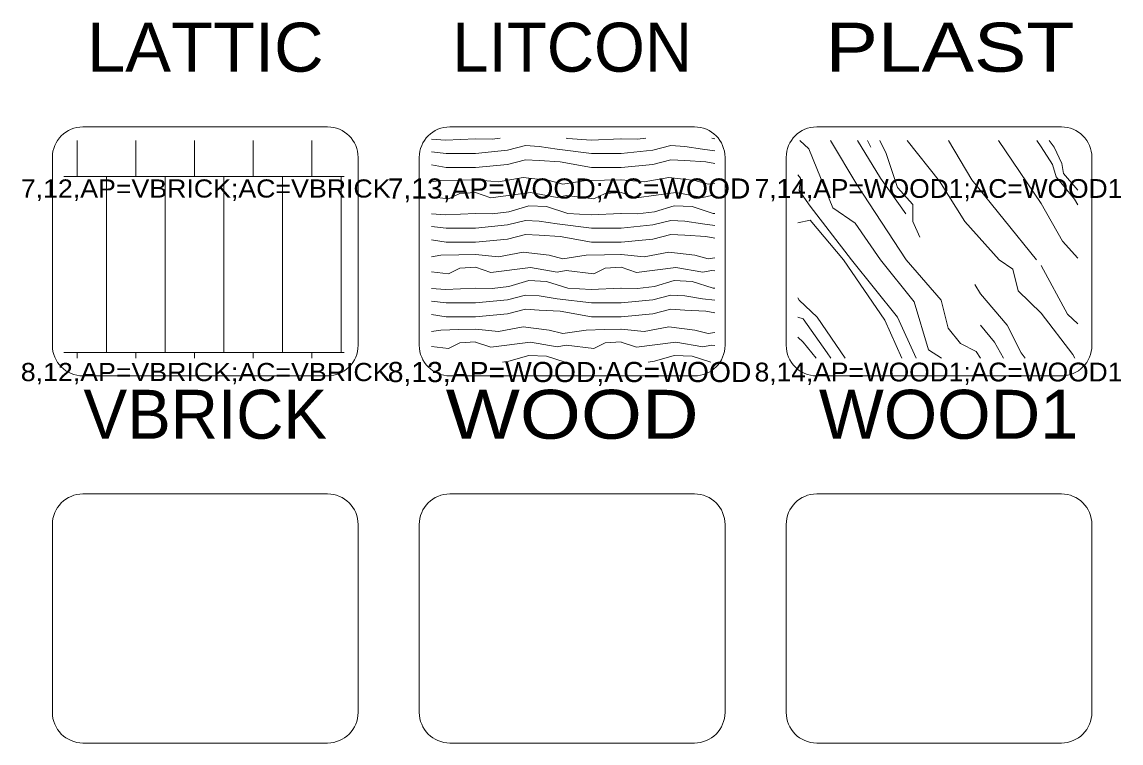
# Model space of a CAD drawing. Extents: x 95935 to 95946.4, y 95971.2 to 95974.7.
# Drawn here: x 95941.636 to 95943.433, y 95971.925 to 95973.103 of the extents above; entities that cross this region are included whole.
import ezdxf
from ezdxf.enums import TextEntityAlignment as Align

# ---------------------------------------------------------------- set-up
doc = ezdxf.new("R2010")
doc.units = 0
doc.header["$LTSCALE"] = 0.013
for name, color, linetype, lineweight in [('1', 7, 'Continuous', 13), ('6', 7, 'Continuous', 13), ('63', 7, 'Continuous', 13)]:
    doc.layers.add(name, color=color, linetype=linetype, lineweight=lineweight)
doc.layers.add('20', color=7, linetype='Continuous')

msp = doc.modelspace()

# ---------------------------------------------------------------- linework, layer by layer
at = {"layer": '1'}
for p, q in [((95941.7357, 95972.9318), (95942.1357, 95972.9318)), ((95942.3357, 95972.9318), (95942.7357, 95972.9318)), ((95942.9357, 95972.9318), (95943.3357, 95972.9318)), ((95941.6857, 95972.5747), (95941.6857, 95972.8818)), ((95942.1857, 95972.8818), (95942.1857, 95972.5747)), ((95942.2857, 95972.5747), (95942.2857, 95972.8818)), ((95942.7857, 95972.8818), (95942.7857, 95972.5747)), ((95942.8857, 95972.5747), (95942.8857, 95972.8818)), ((95943.3857, 95972.8818), (95943.3857, 95972.5747)), ((95942.1357, 95972.5247), (95941.7357, 95972.5247)), ((95942.7357, 95972.5247), (95942.3357, 95972.5247)), ((95943.3357, 95972.5247), (95942.9357, 95972.5247)), ((95941.7357, 95972.3318), (95942.1357, 95972.3318)), ((95942.3357, 95972.3318), (95942.7357, 95972.3318)), ((95942.9357, 95972.3318), (95943.3357, 95972.3318)), ((95941.6857, 95971.9747), (95941.6857, 95972.2818)), ((95942.1857, 95972.2818), (95942.1857, 95971.9747)), ((95942.2857, 95971.9747), (95942.2857, 95972.2818)), ((95942.7857, 95972.2818), (95942.7857, 95971.9747)), ((95942.8857, 95971.9747), (95942.8857, 95972.2818)), ((95943.3857, 95972.2818), (95943.3857, 95971.9747)), ((95942.1357, 95971.9247), (95941.7357, 95971.9247)), ((95942.7357, 95971.9247), (95942.3357, 95971.9247)), ((95943.3357, 95971.9247), (95942.9357, 95971.9247))]:
    msp.add_line(p, q, dxfattribs=at)
for centre, start, end in [((95941.7357, 95972.8818), 90, 180), ((95942.1357, 95972.8818), 0, 90), ((95942.3357, 95972.8818), 90, 180), ((95942.7357, 95972.8818), 0, 90), ((95942.9357, 95972.8818), 90, 180), ((95943.3357, 95972.8818), 0, 90), ((95941.7357, 95972.5747), 180, 270), ((95942.1357, 95972.5747), 270, 0), ((95942.3357, 95972.5747), 180, 270), ((95942.7357, 95972.5747), 270, 0), ((95942.9357, 95972.5747), 180, 270), ((95943.3357, 95972.5747), 270, 0), ((95941.7357, 95972.2818), 90, 180), ((95942.1357, 95972.2818), 0, 90), ((95942.3357, 95972.2818), 90, 180), ((95942.7357, 95972.2818), 0, 90), ((95942.9357, 95972.2818), 90, 180), ((95943.3357, 95972.2818), 0, 90), ((95941.7357, 95971.9747), 180, 270), ((95942.1357, 95971.9747), 270, 0), ((95942.3357, 95971.9747), 180, 270), ((95942.7357, 95971.9747), 270, 0), ((95942.9357, 95971.9747), 180, 270), ((95943.3357, 95971.9747), 270, 0)]:
    msp.add_arc(centre, 0.05, start, end, dxfattribs=at)
at = {"layer": '6'}
for p, q in [((95941.7261, 95972.8509), (95941.7261, 95972.9094)), ((95941.8221, 95972.8509), (95941.8221, 95972.9094)), ((95941.9181, 95972.8509), (95941.9181, 95972.9094)), ((95942.0141, 95972.8509), (95942.0141, 95972.9094)), ((95942.1101, 95972.8509), (95942.1101, 95972.9094)), ((95943.0239, 95972.8986), (95943.0186, 95972.9094)), ((95943.3028, 95972.8063), (95943.2327, 95972.9094)), ((95943.3028, 95972.8993), (95943.2956, 95972.9094)), ((95941.7046, 95972.8509), (95942.1628, 95972.8509)), ((95941.7741, 95972.5629), (95941.7741, 95972.8509)), ((95941.8701, 95972.5629), (95941.8701, 95972.8509)), ((95941.9661, 95972.5629), (95941.9661, 95972.8509)), ((95942.0621, 95972.5629), (95942.0621, 95972.8509)), ((95942.1581, 95972.5629), (95942.1581, 95972.8509)), ((95941.7046, 95972.5629), (95942.1628, 95972.5629)), ((95941.7261, 95972.5536), (95941.7261, 95972.5629)), ((95941.8221, 95972.5536), (95941.8221, 95972.5629)), ((95941.9181, 95972.5536), (95941.9181, 95972.5629)), ((95942.0141, 95972.5536), (95942.0141, 95972.5629)), ((95942.1101, 95972.5536), (95942.1101, 95972.5629))]:
    msp.add_line(p, q, dxfattribs=at)
for points in [[(95942.3774, 95972.9124), (95942.3286, 95972.9103), (95942.3059, 95972.9116)], [(95942.418, 95972.9133), (95942.4047, 95972.9117), (95942.3778, 95972.9124)], [(95942.3778, 95972.8884), (95942.4298, 95972.8935), (95942.4592, 95972.9011), (95942.482, 95972.8998), (95942.511, 95972.8952), (95942.5674, 95972.8884), (95942.6153, 95972.8884)], [(95942.6153, 95972.9124), (95942.5666, 95972.9103), (95942.5286, 95972.9125), (95942.5261, 95972.9133)], [(95942.656, 95972.9133), (95942.6426, 95972.9117), (95942.6158, 95972.9124)], [(95942.6158, 95972.8884), (95942.6677, 95972.8935), (95942.6972, 95972.9011), (95942.7199, 95972.8998), (95942.749, 95972.8952), (95942.7689, 95972.8928)], [(95942.7689, 95972.9124), (95942.7665, 95972.9125), (95942.764, 95972.9133)], [(95942.908, 95972.9094), (95942.9228, 95972.8961), (95942.9619, 95972.7997), (95942.9987, 95972.7743), (95943.0399, 95972.7145)], [(95943.0819, 95972.7145), (95943.001, 95972.8377), (95942.9584, 95972.9094)], [(95943.0814, 95972.7895), (95943.04, 95972.8479), (95943.0022, 95972.9094)], [(95943.0387, 95972.9094), (95943.0492, 95972.8885), (95943.0676, 95972.8327), (95943.0929, 95972.8048), (95943.0929, 95972.7769), (95943.1044, 95972.7515)], [(95943.0835, 95972.9094), (95943.1366, 95972.8428), (95943.1779, 95972.7769), (95943.2341, 95972.7145)], [(95943.2953, 95972.7145), (95943.1894, 95972.8454), (95943.1514, 95972.9094)], [(95943.3628, 95972.8043), (95943.3574, 95972.8136), (95943.3272, 95972.8503), (95943.3212, 95972.8703), (95943.3028, 95972.8993)], [(95943.3628, 95972.8283), (95943.3393, 95972.8553), (95943.3363, 95972.872), (95943.3242, 95972.8987), (95943.3155, 95972.9094)], [(95942.3059, 95972.8912), (95942.3295, 95972.8884), (95942.3774, 95972.8884)], [(95942.3059, 95972.8695), (95942.3295, 95972.8653), (95942.3774, 95972.8653)], [(95942.3778, 95972.8653), (95942.4298, 95972.8704), (95942.4592, 95972.8779), (95942.482, 95972.8767), (95942.5161, 95972.8745), (95942.5674, 95972.8653), (95942.6153, 95972.8653)], [(95942.6158, 95972.8653), (95942.6677, 95972.8704), (95942.6972, 95972.8779), (95942.7199, 95972.8767), (95942.7541, 95972.8745), (95942.7689, 95972.8718)], [(95942.3059, 95972.8417), (95942.3208, 95972.844), (95942.3505, 95972.8446), (95942.3774, 95972.8453)], [(95942.3778, 95972.8453), (95942.4154, 95972.8417), (95942.4556, 95972.8489), (95942.4982, 95972.844), (95942.5202, 95972.8381), (95942.5587, 95972.844), (95942.5885, 95972.8446), (95942.6153, 95972.8453)], [(95942.6158, 95972.8453), (95942.6534, 95972.8417), (95942.6936, 95972.8489), (95942.7361, 95972.844), (95942.7581, 95972.8381), (95942.7689, 95972.8398)], [(95942.9046, 95972.8535), (95942.909, 95972.8479), (95942.9067, 95972.8276), (95942.9251, 95972.8022), (95942.9923, 95972.7145)], [(95942.3059, 95972.8173), (95942.3334, 95972.814), (95942.3518, 95972.8228), (95942.3778, 95972.8244)], [(95942.3778, 95972.8244), (95942.4029, 95972.8158), (95942.4674, 95972.8243), (95942.5113, 95972.8164), (95942.5257, 95972.8194), (95942.5713, 95972.814), (95942.5898, 95972.8228), (95942.6158, 95972.8244)], [(95942.6158, 95972.8244), (95942.6408, 95972.8158), (95942.7054, 95972.8243), (95942.7493, 95972.8164), (95942.7637, 95972.8194), (95942.7689, 95972.8188)], [(95942.6153, 95972.7903), (95942.5666, 95972.7882), (95942.5286, 95972.7903), (95942.4938, 95972.8014), (95942.4647, 95972.8025), (95942.4322, 95972.7929), (95942.4047, 95972.7896), (95942.3778, 95972.7903)], [(95942.7689, 95972.7902), (95942.7665, 95972.7903), (95942.7318, 95972.8014), (95942.7027, 95972.8025), (95942.6702, 95972.7929), (95942.6426, 95972.7896), (95942.6158, 95972.7903)], [(95943.3628, 95972.7172), (95943.3378, 95972.7452), (95943.3028, 95972.8063)], [(95942.3774, 95972.7903), (95942.3286, 95972.7882), (95942.3059, 95972.7895)], [(95942.3778, 95972.7663), (95942.4298, 95972.7714), (95942.4592, 95972.7789), (95942.482, 95972.7777), (95942.511, 95972.7731), (95942.5674, 95972.7663), (95942.6153, 95972.7663)], [(95942.6158, 95972.7663), (95942.6677, 95972.7714), (95942.6972, 95972.7789), (95942.7199, 95972.7777), (95942.749, 95972.7731), (95942.7689, 95972.7707)], [(95942.9046, 95972.7749), (95942.9251, 95972.7794), (95942.9795, 95972.7145)], [(95942.3059, 95972.7691), (95942.3295, 95972.7663), (95942.3774, 95972.7663)], [(95942.3778, 95972.7432), (95942.4298, 95972.7482), (95942.4592, 95972.7558), (95942.482, 95972.7545), (95942.5161, 95972.7524), (95942.5674, 95972.7432), (95942.6153, 95972.7432)], [(95942.6158, 95972.7432), (95942.6677, 95972.7482), (95942.6972, 95972.7558), (95942.7199, 95972.7545), (95942.7541, 95972.7524), (95942.7689, 95972.7497)], [(95942.3059, 95972.7474), (95942.3295, 95972.7432), (95942.3774, 95972.7432)], [(95942.3059, 95972.7196), (95942.3208, 95972.7218), (95942.3505, 95972.7225), (95942.3774, 95972.7232)], [(95942.3778, 95972.7232), (95942.4154, 95972.7195), (95942.4556, 95972.7268), (95942.4982, 95972.7218), (95942.5202, 95972.716), (95942.5587, 95972.7218), (95942.5885, 95972.7225), (95942.6153, 95972.7232)], [(95942.6158, 95972.7232), (95942.6534, 95972.7195), (95942.6936, 95972.7268), (95942.7361, 95972.7218), (95942.7581, 95972.716), (95942.7689, 95972.7176)], [(95942.3059, 95972.6951), (95942.3334, 95972.6918), (95942.3518, 95972.7007), (95942.3778, 95972.7023)], [(95942.3778, 95972.7023), (95942.4029, 95972.6937), (95942.4674, 95972.7021), (95942.5113, 95972.6943), (95942.5257, 95972.6972), (95942.5713, 95972.6918), (95942.5898, 95972.7007), (95942.6158, 95972.7023)], [(95942.6158, 95972.7023), (95942.6408, 95972.6937), (95942.7054, 95972.7021), (95942.7493, 95972.6943), (95942.7637, 95972.6972), (95942.7689, 95972.6966)], [(95943.075, 95972.5536), (95943.0469, 95972.6156), (95942.9795, 95972.7145)], [(95942.9923, 95972.7145), (95943.0676, 95972.6206), (95943.098, 95972.5536)], [(95943.1396, 95972.5536), (95943.1182, 95972.5674), (95943.0952, 95972.646), (95943.0399, 95972.7145)], [(95943.0819, 95972.7145), (95943.1389, 95972.6485), (95943.1504, 95972.6029), (95943.171, 95972.5775), (95943.1963, 95972.5648), (95943.2036, 95972.5536)], [(95943.3028, 95972.627), (95943.2653, 95972.6638), (95943.2561, 95972.6993), (95943.2341, 95972.7145)], [(95943.3028, 95972.7053), (95943.3455, 95972.6257), (95943.3628, 95972.6096)], [(95942.3774, 95972.6682), (95942.3286, 95972.6661), (95942.3059, 95972.6674)], [(95942.6153, 95972.6682), (95942.5666, 95972.6661), (95942.5286, 95972.6682), (95942.4938, 95972.6793), (95942.4647, 95972.6804), (95942.4322, 95972.6708), (95942.4047, 95972.6675), (95942.3778, 95972.6682)], [(95942.7689, 95972.6681), (95942.7665, 95972.6682), (95942.7318, 95972.6793), (95942.7027, 95972.6804), (95942.6702, 95972.6708), (95942.6426, 95972.6675), (95942.6158, 95972.6682)], [(95943.2764, 95972.5536), (95943.2699, 95972.5623), (95943.2469, 95972.6079), (95943.2032, 95972.6587), (95943.194, 95972.6739)], [(95942.3778, 95972.6442), (95942.4298, 95972.6492), (95942.4592, 95972.6568), (95942.482, 95972.6556), (95942.511, 95972.6509), (95942.5674, 95972.6442), (95942.6153, 95972.6442)], [(95942.6158, 95972.6442), (95942.6677, 95972.6492), (95942.6972, 95972.6568), (95942.7199, 95972.6556), (95942.749, 95972.6509), (95942.7689, 95972.6485)], [(95942.9046, 95972.6524), (95942.9067, 95972.6485), (95942.9366, 95972.6206), (95942.9822, 95972.5536)], [(95942.3059, 95972.647), (95942.3295, 95972.6442), (95942.3774, 95972.6442)], [(95942.3778, 95972.6211), (95942.4298, 95972.6261), (95942.4592, 95972.6337), (95942.482, 95972.6324), (95942.5161, 95972.6303), (95942.5674, 95972.6211), (95942.6153, 95972.6211)], [(95942.6158, 95972.6211), (95942.6677, 95972.6261), (95942.6972, 95972.6337), (95942.7199, 95972.6324), (95942.7541, 95972.6303), (95942.7689, 95972.6276)], [(95942.3059, 95972.6253), (95942.3295, 95972.6211), (95942.3774, 95972.6211)], [(95942.9046, 95972.6206), (95942.9136, 95972.6181), (95942.9527, 95972.5623), (95942.9587, 95972.5536)], [(95943.3028, 95972.627), (95943.3547, 95972.5597), (95943.3576, 95972.5536)], [(95942.3059, 95972.5974), (95942.3208, 95972.5997), (95942.3505, 95972.6004), (95942.3774, 95972.6011)], [(95942.3778, 95972.6011), (95942.4154, 95972.5974), (95942.4556, 95972.6047), (95942.4982, 95972.5997), (95942.5202, 95972.5938), (95942.5587, 95972.5997), (95942.5885, 95972.6004), (95942.6153, 95972.6011)], [(95942.6158, 95972.6011), (95942.6534, 95972.5974), (95942.6936, 95972.6047), (95942.7361, 95972.5997), (95942.7581, 95972.5938), (95942.7689, 95972.5955)], [(95943.2412, 95972.5536), (95943.2262, 95972.58), (95943.2032, 95972.6079)], [(95942.3059, 95972.573), (95942.3334, 95972.5697), (95942.3518, 95972.5786), (95942.3778, 95972.5802)], [(95942.3778, 95972.5801), (95942.4029, 95972.5716), (95942.4674, 95972.58), (95942.5113, 95972.5721), (95942.5257, 95972.5751), (95942.5713, 95972.5697), (95942.5898, 95972.5786), (95942.6158, 95972.5802)], [(95942.6158, 95972.5801), (95942.6408, 95972.5716), (95942.7054, 95972.58), (95942.7493, 95972.5721), (95942.7637, 95972.5751), (95942.7689, 95972.5745)], [(95942.9346, 95972.5536), (95942.9136, 95972.58), (95942.9046, 95972.5882)], [(95942.5245, 95972.5474), (95942.4938, 95972.5572), (95942.4647, 95972.5582), (95942.4322, 95972.5486), (95942.4219, 95972.5474)], [(95942.7624, 95972.5474), (95942.7318, 95972.5572), (95942.7027, 95972.5582), (95942.6702, 95972.5486), (95942.6599, 95972.5474)]]:
    msp.add_lwpolyline(points, dxfattribs=at)

# ---------------------------------------------------------------- texts
at = {"layer": '20'}
for s, width, p in [('LATTIC', 1.05, (95941.9358, 95973.022)), (' PLAST', 1.2, (95943.1357, 95973.022)), (' WOOD ', 1.2, (95942.5358, 95972.422)), (' WOOD1', 1.05, (95943.1358, 95972.422))]:
    msp.add_text(s, height=0.08, dxfattribs=dict(at, width=width)).set_placement(p, align=Align.CENTER)
for s, p in [('LITCON', (95942.5358, 95973.022)), ('VBRICK', (95941.9358, 95972.422))]:
    msp.add_text(s, height=0.08, dxfattribs=at).set_placement(p, align=Align.CENTER)
at = {"layer": '63'}
for s, height, width, p in [('7,12,AP=VBRICK;AC=VBRICK', 0.0297, 1.1, (95941.6341, 95972.8162)), ('7,13,AP=WOOD;AC=WOOD', 0.0329, 1.05, (95942.2341, 95972.8146)), ('7,14,AP=WOOD1;AC=WOOD1', 0.0307, 1.05, (95942.8341, 95972.8157)), ('8,12,AP=VBRICK;AC=VBRICK', 0.0297, 1.1, (95941.6341, 95972.5162)), ('8,13,AP=WOOD;AC=WOOD', 0.033, 1.05, (95942.2341, 95972.5146)), ('8,14,AP=WOOD1;AC=WOOD1', 0.0307, 1.05, (95942.8341, 95972.5157))]:
    msp.add_text(s, height=height, dxfattribs=dict(at, width=width)).set_placement(p)

doc.saveas('drawing.dxf')
